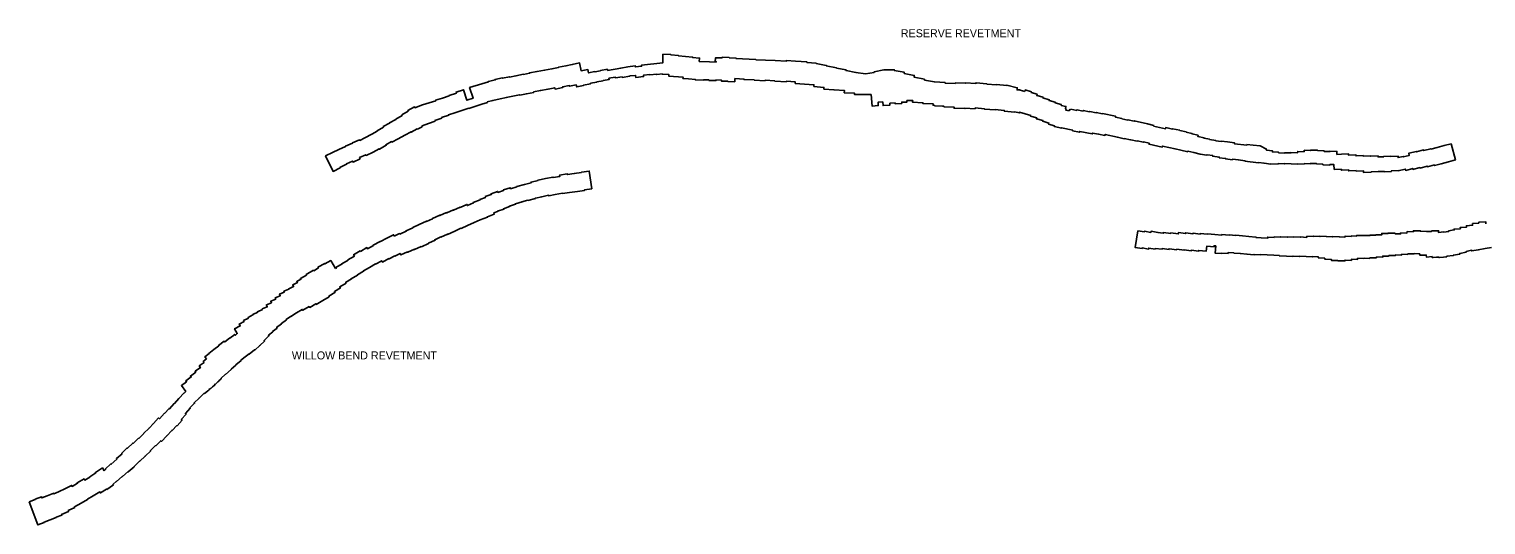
# Model space of a CAD drawing. Extents: x 2650582 to 3923188, y 277893 to 989177.
# Drawn here: x 3507745 to 3536865, y 556922 to 566840 of the extents above; entities that cross this region are included whole.
import ezdxf

# ---------------------------------------------------------------- set-up
doc = ezdxf.new("R2010")
doc.units = 0
doc.layers.add('Level 3', color=7, linetype='Continuous')

msp = doc.modelspace()

# ---------------------------------------------------------------- linework, layer by layer
at = {"layer": 'Level 3'}
for points in [[(3518476, 566107), (3518476, 566105), (3518324, 566077), (3518325, 566069), (3518194, 566043), (3518193, 566045), (3518048, 566018), (3518047, 566020), (3517899, 565992), (3517746, 565962), (3517747, 565957), (3517628, 565934), (3517627, 565938), (3517474, 565907), (3517474, 565905), (3517349, 565881), (3517347, 565886), (3517204, 565857), (3517203, 565862), (3517060, 565835), (3517062, 565825), (3516926, 565792), (3516927, 565785), (3516791, 565747), (3516791, 565746), (3516550, 565671), (3516619, 565457), (3516493, 565418), (3516428, 565625), (3516280, 565579), (3516285, 565561), (3516143, 565514), (3516144, 565508), (3516006, 565461), (3516007, 565459), (3515869, 565415), (3515872, 565406), (3515740, 565363), (3515739, 565365), (3515609, 565323)], [(3521873, 566250), (3521874, 566261), (3521739, 566266), (3521739, 566271), (3521598, 566276), (3521598, 566265), (3521466, 566268), (3521461, 566194), (3521477, 566193), (3521476, 566181), (3521342, 566186), (3521342, 566184), (3521141, 566193), (3521146, 566260), (3521006, 566270), (3521006, 566280), (3520726, 566304), (3520726, 566311), (3520575, 566324), (3520575, 566331), (3520415, 566336), (3520410, 566163), (3519988, 566119), (3519989, 566098), (3519865, 566084), (3519862, 566103), (3519710, 566085), (3519710, 566083), (3519572, 566059), (3519572, 566056), (3519308, 566015), (3519304, 566038), (3519164, 566010), (3519164, 566006), (3519055, 565985), (3519054, 565989), (3518927, 565965), (3518915, 566031), (3518778, 566006), (3518747, 566162), (3518600, 566133), (3518600, 566130), (3518476, 566107)], [(3524828, 566028), (3524828, 566023), (3524634, 565985), (3524635, 565973), (3524463, 565945), (3524272, 565969), (3524272, 565974), (3524075, 566009), (3524076, 566022), (3523884, 566059), (3523885, 566064), (3523679, 566108), (3523680, 566112), (3523477, 566155), (3523476, 566159), (3523293, 566175), (3523293, 566182), (3523062, 566199), (3522882, 566209), (3522881, 566199), (3522657, 566212), (3522467, 566220), (3522467, 566217), (3522273, 566228), (3522273, 566229), (3521873, 566250)], [(3518678, 565726), (3518690, 565684), (3518829, 565713), (3518827, 565720), (3518969, 565747), (3518967, 565756), (3519093, 565780), (3519092, 565783), (3519218, 565806), (3519217, 565809), (3519340, 565833), (3519336, 565858), (3519462, 565877), (3519464, 565866), (3519599, 565887), (3519601, 565873), (3519751, 565896), (3519751, 565902), (3519868, 565915), (3519872, 565875), (3520027, 565890), (3520024, 565917), (3520152, 565933), (3520154, 565927), (3520290, 565941), (3520292, 565931), (3520403, 565943), (3520403, 565938), (3520532, 565934), (3520530, 565900), (3520816, 565879), (3520815, 565855), (3520925, 565846), (3521063, 565833), (3521063, 565824), (3521222, 565818), (3521222, 565824), (3521333, 565822), (3521333, 565815), (3521473, 565811), (3521474, 565823), (3521585, 565819), (3521585, 565800), (3521714, 565796), (3521714, 565792), (3521850, 565788), (3521852, 565854)], [(3521852, 565854), (3522035, 565839), (3522035, 565831), (3522241, 565823), (3522241, 565820), (3522457, 565807), (3522457, 565816), (3522649, 565804), (3522649, 565801), (3522884, 565788), (3522885, 565801), (3523061, 565785), (3523060, 565755), (3523433, 565726), (3523431, 565692), (3523634, 565674), (3523632, 565641), (3523837, 565628), (3523837, 565622), (3524041, 565614), (3524039, 565566), (3524243, 565560), (3524246, 565530), (3524395, 565530), (3524580, 565532)], [(3527646, 565591), (3527556, 565615), (3527556, 565623), (3527493, 565624), (3527497, 565667), (3527291, 565716), (3527290, 565711), (3527085, 565732), (3527084, 565727), (3526892, 565741), (3526892, 565745), (3526675, 565767), (3526672, 565754), (3526466, 565765), (3526465, 565757), (3526259, 565764), (3526258, 565753), (3526054, 565760), (3526054, 565771), (3525840, 565785), (3525840, 565783), (3525644, 565821), (3525643, 565837), (3525439, 565877), (3525439, 565914), (3525237, 565952), (3525238, 565978), (3525038, 566015), (3525037, 566027), (3524828, 566028)], [(3515725, 564953), (3515859, 564999), (3515856, 565009), (3515994, 565055), (3515989, 565074), (3516133, 565121), (3516131, 565126), (3516257, 565167), (3516394, 565213), (3516395, 565209), (3516533, 565256), (3516534, 565254), (3516675, 565299), (3516794, 565336), (3516794, 565338), (3516905, 565372), (3516902, 565384), (3517014, 565414), (3517016, 565409), (3517159, 565442), (3517159, 565444), (3517284, 565470), (3517283, 565473), (3517550, 565525), (3517551, 565520), (3517687, 565547), (3517688, 565545), (3517831, 565574), (3517829, 565585), (3517966, 565612), (3517967, 565609), (3518120, 565637), (3518119, 565640), (3518252, 565666), (3518257, 565641), (3518412, 565670), (3518410, 565686), (3518540, 565710), (3518544, 565695), (3518678, 565726)], [(3524580, 565532), (3524596, 565300), (3524720, 565309), (3524715, 565378), (3524809, 565384), (3524814, 565311), (3524953, 565321), (3524951, 565355), (3525056, 565363), (3525056, 565347), (3525188, 565352), (3525187, 565379), (3525291, 565379), (3525291, 565409), (3525407, 565409), (3525406, 565378), (3525613, 565368), (3525612, 565349), (3525815, 565345), (3525815, 565315), (3525846, 565313), (3525846, 565306), (3526004, 565301), (3526032, 565298), (3526032, 565288), (3526236, 565281), (3526236, 565258), (3526452, 565251), (3526452, 565260), (3526655, 565247), (3526657, 565262), (3526841, 565245), (3526841, 565241), (3527054, 565225), (3527054, 565229), (3527239, 565212), (3527238, 565200), (3527450, 565179), (3527451, 565188)], [(3528374, 565314), (3528378, 565329), (3528253, 565366), (3528257, 565378), (3528133, 565413), (3528136, 565426), (3528009, 565462), (3528013, 565476), (3527887, 565512), (3527894, 565535), (3527777, 565569), (3527781, 565588), (3527656, 565623), (3527646, 565591)], [(3515609, 565323), (3515456, 565268), (3515449, 565282), (3515313, 565211), (3515321, 565195), (3515195, 565124), (3515201, 565110), (3515072, 565036), (3515075, 565032), (3514949, 564962), (3514951, 564958), (3514825, 564890), (3514831, 564879), (3514702, 564804), (3514704, 564801), (3514594, 564738), (3514592, 564741), (3514455, 564666), (3514456, 564664), (3514353, 564613), (3514346, 564625), (3514206, 564562), (3514207, 564559), (3514070, 564496), (3514072, 564493), (3513938, 564430), (3513811, 564370), (3513672, 564303), (3513819, 563994), (3513961, 564062), (3513958, 564070), (3514091, 564135), (3514087, 564143), (3514210, 564201), (3514222, 564178), (3514361, 564245), (3514350, 564270), (3514473, 564327), (3514481, 564312), (3514620, 564381), (3514741, 564446), (3514748, 564435), (3514882, 564515), (3514876, 564525), (3514989, 564590), (3514995, 564580), (3515121, 564647), (3515123, 564645), (3515254, 564719), (3515256, 564716), (3515380, 564786), (3515384, 564778), (3515504, 564844), (3515507, 564840), (3515601, 564888), (3515595, 564901), (3515603, 564906), (3515726, 564949), (3515725, 564953)], [(3529202, 565145), (3529076, 565173), (3529075, 565166), (3528945, 565194), (3528943, 565186), (3528816, 565213), (3528813, 565201), (3528691, 565225), (3528688, 565213), (3528570, 565237), (3528567, 565225), (3528539, 565230), (3528533, 565207), (3528467, 565219), (3528472, 565244), (3528461, 565248), (3528470, 565294), (3528374, 565314)], [(3527451, 565188), (3527537, 565163), (3527541, 565176), (3527766, 565113), (3527762, 565098), (3527887, 565063), (3527882, 565045), (3528009, 565009), (3528006, 564997), (3528130, 564961), (3528125, 564940), (3528244, 564905)], [(3530224, 564900), (3530227, 564914), (3530100, 564943), (3530100, 564946), (3529837, 565005), (3529835, 564998), (3529709, 565025), (3529707, 565020), (3529589, 565045), (3529590, 565050), (3529460, 565079), (3529463, 565095), (3529203, 565150), (3529202, 565145)], [(3528244, 564905), (3528241, 564891), (3528379, 564861), (3528380, 564865), (3528607, 564818), (3528604, 564805), (3528742, 564776), (3528746, 564793), (3528995, 564742), (3528999, 564760), (3529121, 564735)], [(3529121, 564735), (3529122, 564741), (3529251, 564714), (3529256, 564733), (3529499, 564679), (3529498, 564676), (3529636, 564646), (3529637, 564650), (3529764, 564623), (3529765, 564626), (3529892, 564599), (3529893, 564603), (3530018, 564577), (3530020, 564583), (3530137, 564556), (3530132, 564535), (3530394, 564475)], [(3533234, 564417), (3533231, 564388), (3533103, 564393), (3533101, 564367), (3532968, 564372), (3532968, 564363), (3532841, 564368), (3532840, 564360), (3532720, 564367), (3532720, 564376), (3532598, 564382), (3532599, 564407), (3532477, 564421), (3532477, 564424), (3532471, 564425), (3532478, 564439), (3532355, 564504), (3532216, 564519), (3532216, 564515), (3532087, 564530), (3532085, 564518), (3531837, 564546), (3531839, 564568), (3531700, 564585), (3531700, 564582), (3531574, 564597), (3531573, 564591), (3531470, 564603), (3531470, 564611), (3531343, 564633), (3531343, 564638), (3531233, 564657), (3531234, 564662), (3531108, 564691), (3531113, 564716), (3530987, 564746), (3530988, 564753), (3530876, 564780), (3530877, 564782), (3530744, 564812), (3530744, 564815), (3530599, 564847), (3530598, 564841), (3530466, 564870), (3530461, 564847), (3530224, 564900)], [(3530394, 564475), (3530401, 564500), (3530652, 564442), (3530653, 564444), (3530769, 564417), (3530769, 564415), (3530906, 564385), (3530909, 564399), (3531024, 564373), (3531024, 564370), (3531157, 564338), (3531290, 564318), (3531292, 564326), (3531406, 564308), (3531406, 564295), (3531535, 564281), (3531534, 564267), (3531662, 564252), (3531661, 564244), (3531800, 564227), (3531802, 564239), (3531919, 564225), (3531919, 564223), (3532048, 564207), (3532047, 564198), (3532319, 564164), (3532320, 564173), (3532430, 564160), (3532430, 564156), (3532568, 564140), (3532569, 564145), (3532710, 564140), (3532711, 564148), (3532840, 564143), (3532841, 564150), (3532970, 564144), (3532970, 564146), (3533100, 564140), (3533101, 564146), (3533230, 564138), (3533231, 564153)], [(3533885, 564332), (3533888, 564394), (3533747, 564400), (3533746, 564390), (3533630, 564394), (3533630, 564406), (3533501, 564410), (3533501, 564416), (3533360, 564421), (3533360, 564411), (3533234, 564417)], [(3533832, 564029), (3533978, 564036), (3533979, 564015), (3534124, 564022), (3534124, 564004), (3534270, 564011), (3534271, 563998), (3534418, 564005), (3534419, 563971), (3534575, 563978), (3534575, 563986), (3534711, 563992), (3534712, 563988), (3534835, 563994), (3534835, 563986), (3534976, 563992), (3534975, 564004), (3535113, 564009), (3535114, 564007), (3535255, 564039), (3535262, 564013), (3535402, 564053), (3535407, 564033), (3535548, 564069), (3535551, 564061), (3535692, 564099), (3535696, 564086), (3535836, 564123), (3535840, 564111), (3535973, 564146), (3535973, 564145), (3536116, 564182), (3536116, 564186), (3536256, 564222), (3536174, 564546)], [(3536174, 564546), (3536033, 564509), (3536032, 564511), (3535889, 564473), (3535889, 564472), (3535765, 564440), (3535763, 564447), (3535622, 564410), (3535620, 564422), (3535479, 564384), (3535476, 564394), (3535325, 564356), (3535335, 564313), (3535214, 564282), (3535212, 564292), (3535111, 564269), (3535110, 564300), (3534963, 564293), (3534963, 564299), (3534823, 564293), (3534823, 564287), (3534711, 564282), (3534710, 564303), (3534563, 564296), (3534563, 564303), (3534415, 564297), (3534415, 564311), (3534269, 564304), (3534268, 564322), (3534122, 564315), (3534121, 564343), (3533976, 564337), (3533976, 564337), (3533885, 564332)], [(3533231, 564153), (3533358, 564147), (3533359, 564154), (3533480, 564149), (3533480, 564142), (3533608, 564136), (3533607, 564125), (3533746, 564119), (3533747, 564132), (3533828, 564129), (3533832, 564029)], [(3516861, 563489), (3516984, 563531), (3516979, 563547), (3517108, 563592), (3517114, 563574), (3517230, 563614), (3517227, 563623), (3517362, 563667), (3517369, 563647), (3517495, 563686), (3517494, 563690), (3517644, 563729), (3517644, 563729), (3517780, 563764), (3517777, 563779), (3517918, 563812), (3517917, 563819), (3518064, 563848), (3518064, 563851), (3518218, 563881), (3518220, 563870), (3518353, 563891), (3518349, 563918), (3518503, 563943), (3518506, 563930), (3518640, 563949), (3518640, 563952), (3518786, 563973), (3518785, 563977), (3518941, 563999), (3518992, 563643)], [(3515043, 562700), (3515151, 562748), (3515155, 562739), (3515284, 562795), (3515280, 562805), (3515413, 562865), (3515412, 562868), (3515543, 562928), (3515541, 562934), (3515685, 562999), (3515688, 562992), (3515810, 563047), (3515808, 563053), (3515952, 563119), (3515955, 563110), (3516088, 563171), (3516092, 563162), (3516225, 563222), (3516228, 563215), (3516362, 563275), (3516363, 563272), (3516495, 563332), (3516505, 563311), (3516627, 563364), (3516624, 563372), (3516759, 563424), (3516757, 563428), (3516867, 563471), (3516861, 563489)], [(3518992, 563643), (3518846, 563622), (3518847, 563612), (3518705, 563591), (3518549, 563569), (3518548, 563574), (3518408, 563551), (3518407, 563555), (3518263, 563532), (3518131, 563506), (3518130, 563515), (3517991, 563487), (3517865, 563458), (3517866, 563452), (3517716, 563413), (3517715, 563417), (3517597, 563387), (3517598, 563385), (3517467, 563345), (3517468, 563340), (3517345, 563300), (3517349, 563289), (3517228, 563247), (3517231, 563237), (3517109, 563195), (3517110, 563190), (3517033, 563163)], [(3517033, 563163), (3517042, 563140), (3516907, 563087), (3516910, 563080), (3516761, 563022), (3516761, 563022), (3516639, 562970), (3516639, 562970), (3516510, 562912), (3516510, 562912), (3516378, 562852), (3516377, 562855), (3516256, 562800), (3516256, 562800), (3516111, 562734), (3516108, 562739), (3515977, 562680), (3515976, 562683), (3515854, 562627), (3515859, 562615), (3515728, 562555), (3515729, 562553), (3515585, 562487), (3515583, 562490), (3515450, 562430), (3515448, 562435), (3515313, 562376), (3515310, 562383), (3515172, 562323), (3515159, 562351), (3515058, 562300), (3515055, 562305)], [(3536865, 562947), (3536862, 562985), (3536722, 562975), (3536723, 562958), (3536599, 562950), (3536601, 562915), (3536477, 562906), (3536478, 562880), (3536353, 562871), (3536355, 562846), (3536231, 562838), (3536232, 562821), (3536118, 562801)], [(3513871, 562048), (3513883, 562055), (3513876, 562068), (3513999, 562141), (3513996, 562147), (3514120, 562220), (3514118, 562224), (3514246, 562300), (3514231, 562325), (3514364, 562403), (3514369, 562394), (3514496, 562468), (3514508, 562447), (3514629, 562514), (3514625, 562520), (3514763, 562594), (3514766, 562588), (3514896, 562658), (3514898, 562655), (3515029, 562726), (3515043, 562700)], [(3529911, 562805), (3529854, 562472), (3529992, 562449), (3529994, 562461), (3530122, 562438), (3530126, 562459), (3530254, 562438), (3530256, 562452), (3530392, 562437), (3530393, 562449), (3530533, 562433), (3530534, 562445), (3530687, 562426), (3530688, 562438), (3530833, 562418), (3530833, 562426), (3530977, 562407), (3530979, 562417), (3531123, 562398), (3531125, 562413), (3531276, 562398), (3531285, 562497), (3531431, 562483), (3531433, 562505), (3531464, 562502)], [(3532266, 562669), (3532267, 562680), (3532128, 562694), (3532128, 562690), (3531998, 562704), (3531998, 562701), (3531864, 562715), (3531864, 562711), (3531735, 562722), (3531735, 562718), (3531590, 562733), (3531589, 562718), (3531444, 562732), (3531444, 562729), (3531298, 562744), (3531298, 562736), (3531152, 562750), (3531151, 562737), (3531011, 562756), (3531010, 562745), (3530865, 562765), (3530863, 562750), (3530719, 562768), (3530716, 562744), (3530567, 562763), (3530566, 562753), (3530419, 562770), (3530417, 562757), (3530309, 562769), (3530309, 562772), (3530173, 562795), (3530169, 562773), (3530040, 562795), (3530038, 562784), (3529911, 562805)], [(3534285, 562700), (3534175, 562704), (3534175, 562699), (3534173, 562699), (3534173, 562693), (3534051, 562697), (3534051, 562696), (3534049, 562696), (3534048, 562679), (3533938, 562683), (3533938, 562686), (3533795, 562691), (3533795, 562681), (3533676, 562690), (3533675, 562689), (3533546, 562698), (3533546, 562689), (3533417, 562698), (3533416, 562688), (3533287, 562697), (3533285, 562674), (3533156, 562683), (3533156, 562675), (3533026, 562684), (3533025, 562675), (3532895, 562685), (3532894, 562676), (3532763, 562685), (3532763, 562676), (3532634, 562685), (3532633, 562671), (3532506, 562680), (3532504, 562655), (3532373, 562665), (3532373, 562661), (3532266, 562669)], [(3536118, 562801), (3536120, 562789), (3536026, 562778), (3536025, 562782), (3535919, 562770), (3535919, 562807), (3535780, 562804), (3535780, 562791), (3535679, 562789), (3535679, 562793), (3535555, 562795), (3535555, 562805), (3535416, 562807), (3535416, 562787), (3535289, 562790), (3535288, 562760), (3535160, 562762), (3535159, 562744), (3535051, 562746), (3535051, 562756), (3534910, 562759), (3534910, 562750), (3534785, 562752), (3534785, 562721), (3534663, 562723), (3534663, 562715), (3534551, 562718), (3534551, 562710), (3534427, 562714), (3534427, 562710), (3534426, 562710), (3534426, 562711), (3534285, 562713), (3534285, 562700)], [(3531464, 562502), (3531456, 562357), (3531580, 562349), (3531581, 562360), (3531711, 562351), (3531713, 562369), (3531827, 562361), (3531827, 562359), (3531957, 562350), (3531957, 562349), (3532089, 562339), (3532089, 562337), (3532232, 562327), (3532233, 562334), (3532361, 562325), (3532361, 562333), (3532493, 562324), (3532493, 562327), (3532624, 562317), (3532624, 562318), (3532737, 562310), (3532736, 562305), (3532878, 562295), (3532879, 562300), (3533009, 562291), (3533010, 562299), (3533141, 562290), (3533141, 562298), (3533271, 562289), (3533271, 562291), (3533400, 562281), (3533400, 562292), (3533517, 562283), (3533515, 562265), (3533645, 562256), (3533644, 562240), (3533779, 562231), (3533778, 562213), (3533907, 562209), (3533907, 562206), (3534050, 562201), (3534051, 562219), (3534178, 562214), (3534179, 562238), (3534301, 562234), (3534302, 562257), (3534428, 562252), (3534429, 562257), (3534543, 562254), (3534543, 562263), (3534554, 562263), (3534554, 562267), (3534665, 562265), (3534678, 562265), (3534679, 562281), (3534804, 562277), (3534805, 562300), (3534918, 562298), (3534918, 562302), (3534931, 562302), (3534931, 562314), (3535055, 562310), (3535055, 562323), (3535179, 562319), (3535180, 562338)], [(3535180, 562338), (3535304, 562334), (3535305, 562343), (3535419, 562341), (3535419, 562343), (3535431, 562343), (3535431, 562349), (3535527, 562347), (3535545, 562346)], [(3535545, 562346), (3535546, 562315), (3535674, 562319), (3535678, 562278), (3535790, 562288), (3535790, 562273), (3535810, 562273), (3535810, 562269), (3535877, 562275), (3535925, 562276), (3535925, 562273), (3535941, 562274), (3535941, 562270), (3536021, 562279), (3536063, 562282), (3536063, 562284), (3536083, 562286), (3536082, 562295), (3536213, 562310), (3536212, 562317)], [(3536212, 562317), (3536345, 562340), (3536343, 562354), (3536474, 562380), (3536472, 562392), (3536580, 562415), (3536583, 562401), (3536712, 562426), (3536713, 562424), (3536848, 562450), (3536848, 562448), (3536978, 562473)], [(3512313, 561178), (3512309, 561187), (3512408, 561231), (3512404, 561241), (3512504, 561283), (3512487, 561324), (3512587, 561366), (3512575, 561396), (3512675, 561439), (3512664, 561464), (3512764, 561506), (3512751, 561540), (3512845, 561578), (3512838, 561594), (3512938, 561638), (3512934, 561647), (3513032, 561690), (3513015, 561727), (3513107, 561770), (3513095, 561794), (3513178, 561836), (3513169, 561851), (3513290, 561920), (3513284, 561932), (3513429, 562015), (3513434, 562007), (3513527, 562061), (3513519, 562075), (3513653, 562152), (3513658, 562142), (3513775, 562210), (3513871, 562048)], [(3515055, 562305), (3514941, 562244), (3514938, 562249), (3514808, 562180), (3514794, 562207), (3514671, 562138), (3514670, 562141), (3514550, 562071), (3514549, 562072), (3514427, 562001), (3514430, 561997), (3514306, 561923), (3514308, 561919), (3514185, 561846), (3514188, 561841), (3514072, 561772), (3514080, 561759), (3513954, 561686), (3513968, 561662), (3513846, 561590), (3513857, 561570), (3513736, 561499), (3513744, 561487), (3513616, 561412), (3513618, 561409), (3513485, 561331), (3513477, 561345), (3513353, 561272), (3513342, 561290), (3513214, 561214), (3513204, 561231), (3513091, 561164), (3513092, 561162), (3512974, 561089), (3512971, 561093), (3512884, 561031), (3512888, 561025), (3512787, 560952), (3512791, 560947), (3512691, 560872), (3512701, 560858), (3512612, 560792)], [(3511287, 560243), (3511256, 560282), (3511342, 560349), (3511340, 560351), (3511438, 560428), (3511438, 560429), (3511537, 560506), (3511533, 560511), (3511643, 560597), (3511655, 560582), (3511753, 560659), (3511755, 560656), (3511854, 560733), (3511867, 560716), (3511905, 560748), (3511853, 560844), (3511964, 560903), (3511944, 560940), (3512040, 560991), (3512032, 561008), (3512128, 561059), (3512122, 561071), (3512219, 561121), (3512214, 561130), (3512313, 561178)], [(3512612, 560792), (3512617, 560786), (3512527, 560714), (3512539, 560701), (3512442, 560610), (3512452, 560600), (3512355, 560511), (3512357, 560509), (3512258, 560420), (3512251, 560427), (3512145, 560338), (3512141, 560343), (3512089, 560303), (3512090, 560301)], [(3512090, 560301), (3511978, 560215), (3511983, 560208), (3511876, 560121), (3511879, 560117), (3511782, 560036), (3511785, 560033), (3511670, 559932), (3511667, 559935), (3511579, 559852), (3511585, 559846), (3511537, 559801), (3511539, 559798), (3511517, 559781), (3511473, 559740), (3511472, 559741), (3511441, 559711), (3511444, 559707), (3511409, 559681), (3511372, 559646), (3511367, 559651), (3511349, 559638), (3511340, 559629), (3511343, 559625), (3511309, 559600), (3511253, 559548), (3511246, 559555), (3511143, 559458), (3511143, 559458), (3511043, 559362), (3511051, 559354), (3510959, 559261), (3510965, 559255), (3510869, 559148), (3510882, 559137), (3510787, 559031), (3510802, 559017), (3510701, 558904), (3510696, 558909), (3510601, 558807), (3510597, 558811), (3510497, 558704), (3510496, 558705), (3510388, 558593), (3510377, 558605), (3510276, 558505), (3510273, 558508), (3510169, 558408), (3510176, 558401), (3510066, 558295), (3510062, 558299), (3509955, 558195), (3509954, 558196), (3509841, 558087), (3509843, 558085), (3509727, 557983), (3509722, 557989), (3509610, 557888), (3509607, 557892), (3509490, 557787), (3509487, 557791), (3509424, 557735), (3509433, 557721)], [(3510875, 559588), (3510788, 559708), (3510893, 559784), (3510879, 559805), (3510984, 559881), (3510970, 559900), (3511075, 559977), (3511063, 559994), (3511168, 560070), (3511145, 560101), (3511241, 560171), (3511224, 560193), (3511287, 560243)], [(3509246, 558004), (3509274, 558029), (3509265, 558039), (3509379, 558142), (3509385, 558136), (3509499, 558238), (3509491, 558247), (3509602, 558346), (3509594, 558353), (3509704, 558460), (3509710, 558454), (3509817, 558557), (3509824, 558550), (3509931, 558654), (3509935, 558650), (3510035, 558748), (3510032, 558751), (3510141, 558859), (3510143, 558857), (3510233, 558950), (3510230, 558952), (3510333, 559062), (3510351, 559045), (3510451, 559154), (3510453, 559152), (3510542, 559251), (3510551, 559242), (3510646, 559348), (3510648, 559347), (3510739, 559448), (3510734, 559453), (3510841, 559562), (3510844, 559558), (3510875, 559588)], [(3507745, 557385), (3507864, 557429), (3507862, 557433), (3507992, 557481), (3508000, 557461), (3508108, 557501), (3508106, 557506), (3508236, 557555), (3508241, 557542), (3508332, 557581), (3508331, 557581), (3508472, 557650), (3508473, 557647), (3508593, 557712), (3508603, 557693), (3508712, 557756), (3508707, 557764), (3508844, 557842), (3508858, 557817), (3508961, 557878), (3508958, 557882), (3509077, 557961), (3509071, 557970), (3509209, 558061), (3509246, 558004)], [(3509433, 557721), (3509296, 557630), (3509289, 557639), (3509171, 557561), (3509158, 557580), (3509027, 557502), (3509027, 557503), (3508909, 557436), (3508912, 557432), (3508782, 557358), (3508784, 557354), (3508651, 557283), (3508656, 557272), (3508526, 557209), (3508533, 557192), (3508394, 557132), (3508400, 557117), (3508282, 557073), (3508284, 557068), (3508163, 557023), (3508164, 557021), (3508045, 556977), (3508047, 556970), (3507917, 556922), (3507745, 557385)]]:
    msp.add_lwpolyline(points, dxfattribs=at)

# ---------------------------------------------------------------- texts
for s, p in [('RESERVE REVETMENT', (3525170, 566677)), ('WILLOW BEND REVETMENT', (3512996, 560232))]:
    msp.add_text(s, height=160, dxfattribs=at).set_placement(p)

doc.saveas('drawing.dxf')
